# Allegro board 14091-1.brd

Outline 185 x 230 mm; copper layers: TOP, L2GND, L3, L4, L5GND, BOTTOM. Coordinates in mm from the lower left corner of the outline.
Outline path: 0,229 0,154.5 arc(0.59,153.09) 2,152.5 arc(3.41,151.91) 4,150.5 4,133 arc(4.29,132.29) 5,132 27,132 arc(27.71,131.71) 28,131 28,76 arc(27.71,75.29) 27,75 21,75 arc(20.29,74.71) 20,74 20,1 arc(20.29,0.29) 21,0 154,0 arc(154.71,0.29) 155,1 155,14 arc(155.29,14.71) 156,15 169,15 arc(169.71,15.29) 170,16 170,58.9 arc(170.29,59.61) 171,59.9 176,59.9 arc(176.71,60.19) 177,60.9 177,65.9 arc(177.29,66.61) 178,66.9 184,66.9 arc(184.71,67.19) 185,67.9 185,104.34 182,104.34 arc(180.25,106.09) 182,107.84 185,107.84 185,161.4 arc(184.71,162.11) 184,162.4 171,162.4 arc(170.29,162.69) 170,163.4 170,229 arc(169.71,229.71) 169,230 1,230 arc(0.29,229.71) 0,229 ; 24.75,51.4 25.25,51.4 arc(27.5,49.15) 25.25,46.9 24.75,46.9 arc(22.5,49.15) 24.75,51.4 ; 162.75,225.25 arc(165,227.5) 167.25,225.25 167.25,224.75 arc(165,222.5) 162.75,224.75 162.75,225.25

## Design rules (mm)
constraint set DEFAULT: min track width 0.127, pair gap 0.102
net group AUD_LINK_BCLK: nets AUD_LINK_BCLK HDA_BITCLK_CPU
net group CLK_WLAN_N: nets CLK_WLAN_N NGFF_REFCLKN0
net group CLK_WLAN_P: nets CLK_WLAN_P NGFF_REFCLKP0
net group DP_LANE0N_C: nets DP_LANE0N_C EDP_TX_CPU_N0
net group DP_LANE0P_C: nets DP_LANE0P_C EDP_TX_CPU_P0
net group DP_LANE1N_C: nets DP_LANE1N_C EDP_TX_CPU_N1
net group DP_LANE1P_C: nets DP_LANE1P_C EDP_TX_CPU_P1
net group DP_LANE2N_C: nets DP_LANE2N_C EDP_TX_CPU_N2
net group DP_LANE2P_C: nets DP_LANE2P_C EDP_TX_CPU_P2
net group DP_LANE3N_C: nets DP_LANE3N_C EDP_TX_CPU_N3
net group DP_LANE3P_C: nets DP_LANE3P_C EDP_TX_CPU_P3
net group GND: nets GND_AUD VSS_MECH
net group GPU_ODT-MW: nets ODTA0 ODTA1
net group HDMI1_CK+: nets HDMI1_CK+ HDMI1_CK+_C
net group HDMI1_CK-: nets HDMI1_CK- HDMI1_CK-_C
net group HDMI1_D0+: nets HDMI1_D0+ HDMI1_D0+_C
net group HDMI1_D0-: nets HDMI1_D0- HDMI1_D0-_C
net group HDMI1_D1+: nets HDMI1_D1+ HDMI1_D1+_C
net group HDMI1_D1-: nets HDMI1_D1- HDMI1_D1-_C
net group HDMI1_D2+: nets HDMI1_D2+ HDMI1_D2+_C
net group HDMI1_D2-: nets HDMI1_D2- HDMI1_D2-_C
net group HDMI1_DATA_CPU_N0: nets HDMI1_DATA_CPU_N0 HDMI1_DATA_IC_N0
net group HDMI1_DATA_CPU_N1: nets HDMI1_DATA_CPU_N1 HDMI1_DATA_IC_N1
net group HDMI1_DATA_CPU_N2: nets HDMI1_DATA_CPU_N2 HDMI1_DATA_IC_N2
net group HDMI1_DATA_CPU_N3: nets HDMI1_DATA_CPU_N3 HDMI1_DATA_IC_N3
net group HDMI1_DATA_CPU_P0: nets HDMI1_DATA_CPU_P0 HDMI1_DATA_IC_P0
net group HDMI1_DATA_CPU_P1: nets HDMI1_DATA_CPU_P1 HDMI1_DATA_IC_P1
net group HDMI1_DATA_CPU_P2: nets HDMI1_DATA_CPU_P2 HDMI1_DATA_IC_P2
net group HDMI1_DATA_CPU_P3: nets HDMI1_DATA_CPU_P3 HDMI1_DATA_IC_P3
net group HDMI_LANE0_DN: nets HDMI_LANE0_DN HDMI_LANE0_IC_DN
net group HDMI_LANE0_DP: nets HDMI_LANE0_DP HDMI_LANE0_IC_DP
net group HDMI_LANE1_DN: nets HDMI_LANE1_DN HDMI_LANE1_IC_DN
net group HDMI_LANE1_DP: nets HDMI_LANE1_DP HDMI_LANE1_IC_DP
net group HDMI_LANE2_DN: nets HDMI_LANE2_DN HDMI_LANE2_IC_DN
net group HDMI_LANE2_DP: nets HDMI_LANE2_DP HDMI_LANE2_IC_DP
net group HDMI_LANE3_DN: nets HDMI_LANE3_DN HDMI_LANE3_IC_DN
net group HDMI_LANE3_DP: nets HDMI_LANE3_DP HDMI_LANE3_IC_DP
net group HSI_C_DN8: nets HSI_C_DN8 PCIE_RX_CPU_N8
net group HSI_C_DP8: nets HSI_C_DP8 PCIE_RX_CPU_P8
net group HSI_LAN_DN1_R: nets HSI_LAN_DN1_R PCIE_RX_CPU_N4
net group HSI_LAN_DP1_R: nets HSI_LAN_DP1_R PCIE_RX_CPU_P4
net group LAN_MDI2_DN: nets LAN_MDI2_DN LAN_MDI2_DN_R
net group LAN_MDI2_DP: nets LAN_MDI2_DP LAN_MDI2_DP_R
net group LAN_MDI3_DN: nets LAN_MDI3_DN LAN_MDI3_DN_R
net group LAN_MDI3_DP: nets LAN_MDI3_DP LAN_MDI3_DP_R
net group M1_SMB_CLK: nets M1_SMB_CLK SMB_CLK_RESUME
net group M1_SMB_DATA: nets M1_SMB_DATA SMB_DATA_RESUME
net group M_A_CLK0: nets M_A_CLK0 M_A_CLK#0
net group M_A_CLK1: nets M_A_CLK1 M_A_CLK#1
net group M_B_CLK0: nets M_B_CLK0 M_B_CLK#0
net group M_B_DQS0: nets M_B_DQS_DN0 M_B_DQS_DP0
net group M_B_DQS1: nets M_B_DQS_DN1 M_B_DQS_DP1
net group M_B_DQS2: nets M_B_DQS_DN2 M_B_DQS_DP2
net group M_B_DQS3: nets M_B_DQS_DN3 M_B_DQS_DP3
net group M_B_DQS4: nets M_B_DQS_DN4 M_B_DQS_DP4
net group M_B_DQS5: nets M_B_DQS_DN5 M_B_DQS_DP5
net group M_B_DQS6: nets M_B_DQS_DN6 M_B_DQS_DP6
net group M_B_DQS7: nets M_B_DQS_DN7 M_B_DQS_DP7
net group NGFF_PCIE0_RXN: nets NGFF_PCIE0_RXN PCIE_RX_CPU_N5
net group NGFF_PCIE0_RXP: nets NGFF_PCIE0_RXP PCIE_RX_CPU_P5
net group PCIE_TX_CON_N4: nets PCIE_TX_CON_N4 PCIE_TX_CPU_N4
net group PCIE_TX_CON_N8: nets PCIE_TX_CON_N8 PCIE_TX_CPU_N8
net group PCIE_TX_CON_P4: nets PCIE_TX_CON_P4 PCIE_TX_CPU_P4
net group PCIE_TX_CON_P8: nets PCIE_TX_CON_P8 PCIE_TX_CPU_P8
net group PEG_C_RXN0: nets PEG_C_RXN0 PEG_RXN0
net group PEG_C_RXN1: nets PEG_C_RXN1 PEG_RXN1
net group PEG_C_RXN2: nets PEG_C_RXN2 PEG_RXN2
net group PEG_C_RXN3: nets PEG_C_RXN3 PEG_RXN3
net group PEG_C_RXP0: nets PEG_C_RXP0 PEG_RXP0
net group PEG_C_RXP1: nets PEG_C_RXP1 PEG_RXP1
net group PEG_C_RXP2: nets PEG_C_RXP2 PEG_RXP2
net group PEG_C_RXP3: nets PEG_C_RXP3 PEG_RXP3
net group PEG_C_TXN0: nets PEG_C_TXN0 PEG_TXN0
net group PEG_C_TXN1: nets PEG_C_TXN1 PEG_TXN1
net group PEG_C_TXN2: nets PEG_C_TXN2 PEG_TXN2
net group PEG_C_TXN3: nets PEG_C_TXN3 PEG_TXN3
net group PEG_C_TXP0: nets PEG_C_TXP0 PEG_TXP0
net group PEG_C_TXP1: nets PEG_C_TXP1 PEG_TXP1
net group PEG_C_TXP2: nets PEG_C_TXP2 PEG_TXP2
net group PEG_C_TXP3: nets PEG_C_TXP3 PEG_TXP3
net group PEG_CLK_CPU: nets PEG_CLK_CPU PEG_CLK_XDP
net group PEG_CLK_CPU#: nets PEG_CLK_CPU# PEG_CLK_XDP#
net group RCOMP_PCIE: nets PEG_RCOMPN_CPU PEG_RCOMPP_CPU
net group SD_CLK_C_1: nets SD_CLK_C_1 SP3
net group SD_CMD: nets SD_CMD SP4
net group SD_DAT0: nets SD_DAT0 SP2
net group SD_DAT1: nets SD_DAT1 SP1
net group SD_DAT2: nets SD_DAT2 SP6
net group SD_DAT3: nets SD_DAT3 SP5
net group SIDE_USB3_RX0+: nets SIDE_USB3_RX0+ USB30_RX_CPU_P0
net group SIDE_USB3_RX0-: nets SIDE_USB3_RX0- USB30_RX_CPU_N0
net group SIDE_USB3_RX1+: nets SIDE_USB3_RX1+ USB30_RX_CPU_P1
net group SIDE_USB3_RX1-: nets SIDE_USB3_RX1- USB30_RX_CPU_N1
net group SMB_CLK_MAIN: nets SMB_CLK_MAIN XDP_SMBCLK
net group SMB_DATA_MAIN: nets SMB_DATA_MAIN XDP_SMBDAT
net group SPI_CS0_N: nets SPI_CS0_N SPI_CS_CPU_N0
net group STRAP: nets GPP_B18/GSPI0_MOSI GPP_B22/GSPI1_MOSI
net group TRANSFORNER_20_10: nets MCT_R_1 XRF_TDC2
net group USB2_N0: nets USB2_N0 USBP0N_EXT
net group USB2_N1: nets USB2_N1 USB2_OUT_N1
net group USB2_N3: nets USB2_N3 USB3N_EXT
net group USB2_N4: nets USB2_N4 USB_PCH_DN4_NN
net group USB2_N5: nets USB2_N5 USB_TOUCH_N
net group USB2_N6: nets USB2_N6 USB2_NGFF_N6
net group USB2_NGFF_P6: nets USB2_NGFF_P6 USB2_P6
net group USB2_OUT_P1: nets USB2_OUT_P1 USB2_P1
net group USB2_P0: nets USB2_P0 USBP0P_EXT
net group USB2_P3: nets USB2_P3 USB3P_EXT
net group USB2_P4: nets USB2_P4 USB_PCH_DP4_PP
net group USB2_P5: nets USB2_P5 USB_TOUCH_P
net group USB2N_EXT: nets USB2_N2 USB2N_EXT
net group USB2P_EXT: nets USB2_P2 USB2P_EXT
net group AUD_LINK_SDO: nets AUD_LINK_SDO AUD_LINK_SDO_N HDA_SDOUT_CPU
net group AUDIO_AMP-MW: nets TPA3131_FAULT#
net group AUDIO_AMP_15: nets AMP_SPKR_L AMP_SPKR_R AMP_SWITCH_C_L AMP_SWITCH_C_R PORTC_SPK_L PORTC_SPK_L_1 PORTC_SPK_R PORTC_SPK_R_1 SCALAR_OUT_L SCALAR_OUT_L_C SCALAR_OUT_R SCALAR_OUT_R_C SPEAKER1_L1 SPEAKER1_R1 SPKR_IN_L SPKR_IN_R TP3131_GVDD TPA3131_GAIN TPA3131_LINN TPA3131_LINN_1 TPA3131_MUTE TPA3131_PLIMIT TPA3131_RINN TPA3131_RINN_1
net group AUDIO_DMIC_MW: nets AUD_DMIC_CLK AUD_DMIC_CLK_R AUD_DMIC_CLK_R_1 AUD_DMIC_DATA AUD_DMIC_DATA_R
net group AUDIO_HDA: nets AUD_BEEP_C AUD_BEEP_R AUD_LINK_RST_N AUD_LINK_RST_N_R AUD_LINK_SDIN AUD_LINK_SDIN_1 AUD_LINK_SDO_1 AUD_LINK_SDO_R1 AUD_LINK_SYNC BUZZER_SPKR_R HDA_RST#_CPU HDA_SYNC_CPU PCH_AUD_RST_N PCH_AUD_RST_N_1 SENSE_A SENSE_A_C SENSE_B SLEEVE_G SPDIF_IC
net group AUDIO_IO: nets AUD_GP3 EAPD_DEPOP HPOL_CON HPOR_CON HPOUT-JD HPOUT-L HPOUT-R LINE2-VREFO LINEOUT-JD LINEOUT-L LINEOUT-R LINEOUT_C-L LINEOUT_C-R LINEOUT_CON-L LINEOUT_CON-R MIC2-L MIC2-L-1 MIC2-R MIC2-R-1 MIC2-VREFO-L MIC2-VREFO-R
net group AUDIO_IO_REF: nets JDREF MIC-CAP VRP
net group AUDIO_SPK_CN: nets SPKR_L+_C SPKR_L+_SNB SPKR_L-_C SPKR_L-_SNB SPKR_OUT_L+ SPKR_OUT_L- SPKR_OUT_R+ SPKR_OUT_R- SPKR_R+_C SPKR_R+_SNB SPKR_R-_C SPKR_R-_SNB TPA3131_BSNL TPA3131_BSNR TPA3131_BSPL TPA3131_BSPR
net group CARD_READER-MWS: nets SD_CD# SD_WP SP7
net group CFG-MW: nets BPM_CPU_N2 BPM_CPU_N3 CFG0 CFG1 CFG2 CFG3 CFG4 CFG5 CFG6 CFG7 CFG8 CFG9 CFG10 CFG11 CFG12 CFG13 CFG14 CFG15 CFG16 CFG17 CFG18 CFG19
net group CHARGER_4_5-MW: nets AC_IN AC_OK# AC_PRESENT AC_PROTECT AD_IA AD_IA_HW1 AD_IA_HW2 AD_OFF BAT_ALERT BAT_IN# BAT_IN#_1 CHG_ON# SYS_PRES
net group CLOCK-MW: nets CK_P_33M_EC LPC_CLK0 LPC_CLK0_R LPC_CLK1 LPC_CLK1_R LPC_CLK_D SUS_CLK SUS_CLK_PCH
net group CONVERTER_4_5-MW: nets LEDC_ISET LPF RT SSTCMP SSTCMP_1 STATUS VREF
net group CONVERTER_10_10: nets ISEN1 ISEN2 ISEN3 ISEN4 ISW OZ554_PWM RTN1 RTN2 RTN3 RTN4
net group CONVERTER_20_10: nets LDR LDR_1 OZ554_VIN SNB
net group DP_AUXN_C: nets DP_AUXN_C EDP_AUX_CPU_N RTD_PIN122
net group DP_AUXP_C: nets DP_AUXP_C EDP_AUX_CPU_P RTD_PIN121
net group DP_HPD-MW: nets DDSP_B_HPD_CONN DP_HPD EDP_HPD_CPU HDMI1_OUT_HPD HDMI_HDCP_READY HDMI_HPDET
net group FAN_PWM: nets BKLT_ADJ CPU_FAN_CTRL_SIO CPU_FAN_TACH_SIO DPLVDS_PWMIN DPLVDS_PWMOUT L_BKLTCTL LVDS_BL_ADJ SIO_LVDS_BL_ADJ
net group FFS_4_5-MW: nets FALL_INT2 FFS_INT1 FFS_INT1_C FFS_INT2_APU FFS_INT2_C FFS_INT2_Q
net group GPIO_4-MW: nets AC_OK#_C AD_IA_EC AD_IA_HW1_C AD_IA_HW1_EC AD_IA_HW2_C AD_IA_HW2_EC AD_OFF_C ADAPTOR_PSID ADAPTOR_PSID_EC ADAPTOR_PSID_R BAT_IN#_C BIOS_REQ BIST_DISABLE BIST_EN_INV BIST_EN_SIO BIST_ENABLE BIST_ENABLE_1 BIST_PIN25 BOARD1 BOARD2 BOARD3 CHAR_CTL1 CHAR_CTL2 CHAR_CTL3 CHAR_EN CHAR_ILIM_SEL CHAR_USBOC# CHG_ON#_C CR_CLKREQ_R CRCLK_REQ_N DDC_WP DDC_WP_1 DET_HDMI# DET_HDMI_C DISP_UTIL_CPU DPLVDS_HPD EAPD_DEPOP_1 EAPD_DEPOP_2_D EC_PWREN EC_SCI# EC_SMI# EDID_RDY ESPI_RST# EXT_PWR_GATE# FFS_INT1_SIO FIVR_EN_R FLASH_WP GPD2/LAN_WAKE# GPIO GPIO17_THERMAL_INT GPIO19_CTF GPP_B23/SML1ALERT# GPP_C2/SMBALERT# GPP_C5/SML0ALERT# GPU_THERMAL_INT H_RCIN# HDMI_DET1 HDMI_DET_SIO HDMI_IN_DET#_R HP_MUTE IO_SMI_N ITP_PMODE JACK_PSID LAN_DISABLE_N LPC_CLKRUN#_CPU LPC_PME# LPC_PME_N LVDS_DET_A* LVDS_DET_B* MINI_POWER_CTRL MODEL_ID_DET MPCIE_DISABLE_N MS_INS# NGFF_ALERT# NGFF_BT_DISABLE NGFF_DETECT_PCIE NGFF_DETECT_PCIE_C NGFF_DETECT_USB NGFF_DETECT_USB_C NGFFCLK_REQ_N OS_MODE_SEL OSD_BIST_N OSD_CONTROL_SEL OSD_DN OSD_DN_CPU OSD_DN_IC OSD_DN_R OSD_MENU OSD_MENU_CPU OSD_MENU_IC OSD_MENU_R OSD_MENU_SIO OSD_UP OSD_UP_CPU OSD_UP_IC OSD_UP_R PANEL_SEL1_CABLE_C PANEL_SEL1_CABLE_S PANEL_SEL2_CABLE_C PANEL_SEL2_CABLE_S PANEL_SEL3_CABLE_C PANEL_SEL3_CABLE_S PC_MONITOR_SW PCB_VER_ID PCH_CHAR_CTL3 PCIE_CLKREQ1_CPU_N PCIE_CLKREQ2_CPU_N PCIE_CLKREQ3_CPU_N PEG_CLKREQ0_CPU# PEG_CLKREQ4_CPU# PEG_CLKREQ5_CPU# PIRQA# PM_CLKRUN#_EC PROC_SELECT# PSID_D PSID_D_1 PSID_G PW_CLEAR PWR_CHG_AD_OFF PWRCN_DET_N RTD_PIN2 RTD_PIN105 RTD_PIN119 SCALAR_ACK SCALAR_MUTE SD_WAKE#_IC SER_IRQ_R SERIRQ_CPU SHDN_MUTE_AP_CTL SIO_HDD_LED SIO_HDD_LED_1 SIO_INT# SIO_INT_C SIO_SCI# SKEW1 SKEW2 SKEW3 SKTOCC# SLP_WLAN_N SMBUS_MS SPKR_DET SPKR_DET_C THERMAL_SHUT#_SIO USB_OC#0_1 USB_OC#2_3 VSS_AY3 WEBCAM_DET WP_PRO
net group GPIO_PWR_CTRL: nets +V_VREF_PATH1 +V_VREF_PATH2 +V_VREF_PATH3 AD_OFF_L EC_3P3_CTL EC_3P3_CTL_2 EC_3P3_CTL_3 HDA_SPKR HP_MUTE_D HP_MUTE_L LVDS_PU_6_1 ME_CNTL1 N35415300 N35418666 N37189306 PANEL_ON1 PANEL_ON2 PANEL_ON3 PC_MONITOR_SW_G PCH_BKLT_PWM_1 PCH_PWROK_C_1 PCH_PWROK_C_2 PCH_PWROK_C_3 PD4405_A PD4405_K PQ4206_D PQ4406_2 PQ4406_3 PQ4406_5 PQ4406_6 PQ4409_C PQ4409_E PWR_CHG_AD_OFF_R PWR_VDDQ_PG_N PWRGD_3V_B PWRGD_3V_C RSMRST_N_B SA0_DIMA SA0_DIMB SA1_DIMA SA1_DIMB SCALAR_PC_SW1 SCALAR_PC_SW2 SCALAR_PC_SW3 SCALAR_PC_SW4 SCALAR_PC_SW5 SIO_PSON_D SLP_SUSB_C SLP_SUSB_R THERMTRIP#_EC_N TPA3113_SD TPA3113_SD1# VCCIO_EN_C_1 VCCIO_EN_C_2 VCCIO_EN_C_3 VCCIO_EN_C_4 VR_EN_C_1 VR_EN_C_2
net group GPU_ADDRESS-MW: nets MAA0 MAA1 MAA2 MAA3 MAA4 MAA5 MAA6 MAA7 MAA8 MAA9 MAA10 MAA11 MAA12 MAA13 MAA14 MAA_BA0 MAA_BA1 MAA_BA2
net group GPU_CTRL-MW: nets CASA0# CASA1# CKEA0 CKEA1 CSA0#_0 CSA1#_0 RASA0# RASA1# WEA0# WEA1#
net group GPU_DATA-MW: nets DQMA0 DQMA1 DQMA2 DQMA3 DQMA4 DQMA5 DQMA6 DQMA7 MDA0 MDA1 MDA2 MDA3 MDA4 MDA5 MDA6 MDA7 MDA8 MDA9 MDA10 MDA11 MDA12 MDA13 MDA14 MDA15 MDA16 MDA17 MDA18 MDA19 MDA20 MDA21 MDA22 MDA23 MDA24 MDA25 MDA26 MDA27 MDA28 MDA29 MDA30 MDA31 MDA32 MDA33 MDA34 MDA35 MDA36 MDA37 MDA38 MDA39 MDA40 MDA41 MDA42 MDA43 MDA44 MDA45 MDA46 MDA47 MDA48 MDA49 MDA50 MDA51 MDA52 MDA53 MDA54 MDA55 MDA56 MDA57 MDA58 MDA59 MDA60 MDA61 MDA62 MDA63
net group GPU_JTAG_4-6-MW: nets JTAG_TCK_VGA JTAG_TDI_VGA JTAG_TDO_VGA JTAG_TMS_VGA JTAG_TRST#_VGA
net group GPU_OTHER_4-6-MW: nets CLKTESTA CLKTESTA_C CLKTESTB CLKTESTB_C CTF_TRIP CTFB GPIO19_CTF_R GPIO_SVC GPIO_SVD GPIO_SVT GPU_CLKA0_T GPU_CLKA1_T GPU_GPIO16 GPU_SCL GPU_SDA GPU_THERM_SHUTDOWN* GPU_VCC3_CTL GPU_VCC3_CTL_2 GPU_VCC3_CTL_3 GPU_WAKEB GPU_XO_IN GPU_XO_IN2 MEM_CALRP0 MLPS_EN# PCIE_CALR_RX PCIE_CALR_TX PS_0 PS_1 PS_2 PS_3 VRAM_ZQ1 VRAM_ZQ2 VRAM_ZQ3 VRAM_ZQ4
net group GPU_VREF: nets GPU_VREFG MVREFDA MVREFSA VRAM1_VREFCA VRAM1_VREFDQ VRAM2_VREFCA VRAM2_VREFDQ VRAM3_VREFCA VRAM3_VREFDQ VRAM4_VREFCA VRAM4_VREFDQ
net group HDMI-MW: nets CFG DCIN_EN DDCBUF EQ ISET PD_N PRE REXT SB5_33_CT1 SB5_33_CT2
net group HDMI_PWR: nets V_5P0_HDMI_CONN_L
net group LAN_OTHER_4-5-MW: nets LAN_RSET LANCLK_REQ_N LANCLK_REQ_U_N RTL_ISOLATE_N RTL_ISOLATE_N_1 RTL_ISOLATE_N_2
net group LED_10_6: nets BATT_AMBER_LED# BATT_AMBER_LED#_C BATT_WHITE_LED# BATT_WHITE_LED#_C LAN_LEDACT_R# LINK_ACTIVITY_N LINK_PWR PB_IN_SW1 PCH_SATA_LED_1 PCH_SATA_LED_R PWR_LED_YELLOW_C PWR_LED_YELLOW_C2 SATA_LED_N SATA_LED_N_C_1 SIO_GREEN SIO_GREEN_PWM SIO_GREEN_PWM_C_1 SIO_YELLOW SPEED_100*_CON SPEED_100_N SPEED_1000*_CON SPEED_1000_N SUS_LED_GREEN_C SUS_LED_GREEN_C2
net group LPC-MW: nets EXT_RST# FWH_ID0 INIT_3V L_AD0 L_AD1 L_AD2 L_AD3 L_FRAME_N L_FRAME_N_R LAD0_FWH0_EC LAD1_FWH1_EC LAD2_FWH2_EC LAD3_FWH3_EC LDRQ# LDRQ#_EC LFRAMEJ_FW4_EC PLTRST*_EC
net group M_A_CLK TO CTRL: nets M_A_CKE0 M_A_CKE1 M_A_CS#0 M_A_CS#1 M_A_ODT0 M_A_ODT1
net group M_A_CLK TO DQS: nets M_A_DQS_DN0 M_A_DQS_DN1 M_A_DQS_DN2 M_A_DQS_DN3 M_A_DQS_DN4 M_A_DQS_DN5 M_A_DQS_DN6 M_A_DQS_DN7 M_A_DQS_DP0 M_A_DQS_DP1 M_A_DQS_DP2 M_A_DQS_DP3 M_A_DQS_DP4 M_A_DQS_DP5 M_A_DQS_DP6 M_A_DQS_DP7
net group M_A_COMMAND: nets M_A_A0 M_A_A1 M_A_A2 M_A_A3 M_A_A4 M_A_A5 M_A_A6 M_A_A7 M_A_A8 M_A_A9 M_A_A10 M_A_A11 M_A_A12 M_A_A13 M_A_A14 M_A_A15 M_A_BS0 M_A_BS1 M_A_BS2 M_A_CAS# M_A_RAS# M_A_WE#
net group M_A_DATA0: nets M_A_DQ0 M_A_DQ1 M_A_DQ2 M_A_DQ3 M_A_DQ4 M_A_DQ5 M_A_DQ6 M_A_DQ7
net group M_A_DATA1: nets M_A_DQ8 M_A_DQ9 M_A_DQ10 M_A_DQ11 M_A_DQ12 M_A_DQ13 M_A_DQ14 M_A_DQ15
net group M_A_DATA2: nets M_A_DQ16 M_A_DQ17 M_A_DQ18 M_A_DQ19 M_A_DQ20 M_A_DQ21 M_A_DQ22 M_A_DQ23
net group M_A_DATA3: nets M_A_DQ24 M_A_DQ25 M_A_DQ26 M_A_DQ27 M_A_DQ28 M_A_DQ29 M_A_DQ30 M_A_DQ31
net group M_A_DATA4: nets M_A_DQ32 M_A_DQ33 M_A_DQ34 M_A_DQ35 M_A_DQ36 M_A_DQ37 M_A_DQ38 M_A_DQ39
net group M_A_DATA5: nets M_A_DQ40 M_A_DQ41 M_A_DQ42 M_A_DQ43 M_A_DQ44 M_A_DQ45 M_A_DQ46 M_A_DQ47
net group M_A_DATA6: nets M_A_DQ48 M_A_DQ49 M_A_DQ50 M_A_DQ51 M_A_DQ52 M_A_DQ53 M_A_DQ54 M_A_DQ55
net group M_A_DATA7: nets M_A_DQ56 M_A_DQ57 M_A_DQ58 M_A_DQ59 M_A_DQ60 M_A_DQ61 M_A_DQ62 M_A_DQ63
net group M_B_CLK1: nets M_B_CLK#1
net group M_B_CLK TO CONTROL: nets M_B_CKE0 M_B_CKE1 M_B_CLK1 M_B_CS#0 M_B_CS#1 M_B_ODT0 M_B_ODT1
net group M_B_COMMAND: nets M_B_A0 M_B_A1 M_B_A2 M_B_A3 M_B_A4 M_B_A5 M_B_A6 M_B_A7 M_B_A8 M_B_A9 M_B_A10 M_B_A11 M_B_A12 M_B_A13 M_B_A14 M_B_A15 M_B_BS0 M_B_BS1 M_B_BS2 M_B_CAS# M_B_RAS# M_B_WE#
net group M_B_DATA0: nets M_B_DQ0 M_B_DQ1 M_B_DQ2 M_B_DQ3 M_B_DQ4 M_B_DQ5 M_B_DQ6 M_B_DQ7
net group M_B_DATA1: nets M_B_DQ8 M_B_DQ9 M_B_DQ10 M_B_DQ11 M_B_DQ12 M_B_DQ13 M_B_DQ14 M_B_DQ15
net group M_B_DATA2: nets M_B_DQ16 M_B_DQ17 M_B_DQ18 M_B_DQ19 M_B_DQ20 M_B_DQ21 M_B_DQ22 M_B_DQ23
net group M_B_DATA3: nets M_B_DQ24 M_B_DQ25 M_B_DQ26 M_B_DQ27 M_B_DQ28 M_B_DQ29 M_B_DQ30 M_B_DQ31
net group M_B_DATA4: nets M_B_DQ32 M_B_DQ33 M_B_DQ34 M_B_DQ35 M_B_DQ36 M_B_DQ37 M_B_DQ38 M_B_DQ39
net group M_B_DATA5: nets M_B_DQ40 M_B_DQ41 M_B_DQ42 M_B_DQ43 M_B_DQ44 M_B_DQ45 M_B_DQ46 M_B_DQ47
net group M_B_DATA6: nets M_B_DQ48 M_B_DQ49 M_B_DQ50 M_B_DQ51 M_B_DQ52 M_B_DQ53 M_B_DQ54 M_B_DQ55
net group M_B_DATA7: nets M_B_DQ56 M_B_DQ57 M_B_DQ58 M_B_DQ59 M_B_DQ60 M_B_DQ61 M_B_DQ62 M_B_DQ63
net group M_EVENT_4_5-MW: nets SIO_MEM_EVENT_L
net group NGFF_CLCCK-MW: nets NGFF_CLKREQ0_N NGFF_CLKREQ1_N SUSCLK_NGFF
net group NGFF_OTHER-MW: nets NGFF_ALERT_N NGFF_CLKREQ0_NGFF# NGFF_CLKREQ1_N_TP NGFF_PEWAKE0_N NGFF_POWER_CTRL_1 NGFF_W_DISABLE1_N NGFF_W_DISABLE2_N
net group NGFF_PCIE0_TXN: nets NGFF_PCIE0_TXN PCIE_TX_CON_N5 PCIE_TX_CPU_N5
net group NGFF_PCIE0_TXP: nets NGFF_PCIE0_TXP PCIE_TX_CON_P5 PCIE_TX_CPU_P5
net group OSCILLATION-MW: nets 14MHZ_IN_SCALAR 14MHZ_OUT_SCALAR 14MHZ_OUT_SCALAR_C CK_48M_SIO CK_48M_SIO_C LAN_XTALI LAN_XTALO LAN_XTALO_C XTALIN XTALOUT
net group OTHER_4_5-MW: nets 1117 ADJ KDAT MCLK MDAT PB_IN_N_1 SYS_FAN_TACH1_1 SYS_FAN_TACH1_2 SYSTEM_FAN_PWM1_1 TP_DET
net group PANEL_CONTROL-MW: nets BKLT_EN BKLT_EN1 DPLVDS_BL_EN DPLVDS_PANEL_VCC LVDS_DET_B_C* LVDS_PU_5 LVDS_PU_6 LVDS_PU_24 PANEL_ON_1 PANEL_ON_2 PANEL_ON_3 PANEL_ON_4 PANEL_ON_5 PANEL_SEL1_CABLE PANEL_SEL1_CABLE_EC PANEL_SEL2_CABLE PANEL_SEL2_CABLE_EC PANEL_SEL3_CABLE PANEL_SEL3_CABLE_EC S_LVDS_BL_EN SCALAR_SIO_PU
net group PECI_THERMTRIP-MW: nets EC_PECI EC_PROCHOT# H_PROCHOT_N PECI_EC PECI_SIO PROCHOT#_CPU THERMTRIP#_CPU THERMTRIP#_EC TMDS_3V3
net group POWER_10_10: nets 3P3V_SPI CHAR_ILIM_HI CHAR_ILIM_LO DDC5V_HDMI DDC5V_HDMI_R HDMI_OUT_DDC_VCC OCS_48M_1 OCS_48M_2 PWR_VCCSA_VSP_RC RTD2482_VREF SD_VDD2 SIO_VREF VBAT_SIO VCCRTCEXT VSS_AY71
net group POWER_12_10_REF: nets RREF
net group POWER_20_5: nets +19V_AMP_AVCC ADC_1V2 AV12 AV12_L DV12S DV33_18 HDMI_5V PVCC_3V3_SDRAM V_3_CARD VCCK_1V2
net group POWER_40_5: nets 3D3V_AUX_EC AVCC_EC DPLL_PVDD HM_VCCP HM_VCCP_R MPV18 SIO_MAIN_VCC3 SIO_VCORE SPV10 SPV18
net group POWER_50_5: nets 1V_EOPIO 1V_VCCPRIM_CORE 3D3V_AUX_S5 3D3V_VGA_S0 DPLL_VDDC USBVCCTP
net group POWER_CPU_PLL_10_5: nets 1D8V_EDRAM 1D8V_SIP_S5 1D8V_VCCPGPPF 1D35V_VCCSFR_OC 1D35V_VDDQ_CPUCLK 1V_CPU_XDP_AB 1V_CPU_XDP_CD 1V_DCPDSW 1V_SIP_S5 1V_VCC19P2 1V_VCC24TBT 1V_VCCAMPHYPLL 1V_VCCAPLL 1V_VCCAPLLEBB 1V_VCCDTS 1V_VCCF24NS 1V_VCCF100 1V_VCCF100OC 1V_VCCF135 1V_VCCFHV 1V_VCCFUSEPRG 1V_VCCMPHYAON 1V_VCCSFR 1V_VCCSTG 1V_XDP_S5 3D3V_1D8V_VCCHDA 3D3V_1D8V_VCCPGPPA 3D3V_1D8V_VCCPGPPD 3D3V_1D8V_VCCPSPI 3D3V_VCCPGPPB 3D3V_VCCPGPPC 3D3V_VCCPGPPE 3D3V_VCCPGPPG 3D3V_VCCPRIM 3D3V_VCCPRTCPRIM +VCCPRTC_3P3
net group POWER_CPU_PLL_20_5: nets 1V_VCCPRIM 1V_VCCSRAM 3D3V_VCCPDSW
net group POWER_RTC_10_10: nets V_3P0_BAT_VREG VBAT1 VBAT1_R VBAT2
net group PWM_10_10: nets 62882_COMP_R 62882_FB_VSEN 62882_NTC_R AD+_G_1 AD+_G_2 AUD_LINK_RST_N_2 BIST_DISABLE_1 BIST_EN DC_IN_D DDR_VREF_S3 EAPD_DEPOP_2 LAN_DISABLE_N_1 LAN_DISABLE_N_2 LED_5VSB OSD_BIST_N_1 PRW_VGA_CORE_RBIAS PSYS PWR_0D95V_VGA_FB PWR_0D95V_VGA_FB_R1 PWR_0D95V_VGA_FB_R2 PWR_1D0V_CS PWR_1D0V_FB PWR_1D0V_FB_R PWR_1D0V_RF PWR_1D8V_EN PWR_1D8V_FB PWR_1D8V_FB_1 PWR_1D8V_VBYP PWR_1D8V_VOUT PWR_1D8V_VOUT_1 PWR_1D35V_VGA_FB_M PWR_1D35V_VGA_FB_M1 PWR_3D3V_ENTRIP2 PWR_3D3V_FB PWR_3D3V_FB2 PWR_5V3D3V_ENLDO PWR_5V3D3V_TON PWR_5V3V_SECFB PWR_5V_ENTRIP1 PWR_5V_FB1 PWR_CHG_ACDET PWR_CHG_CMPIN PWR_CHG_CMPIN_R PWR_CHG_CMPIN_RR PWR_CHG_ILIM PWR_CHG_IOUT PWR_CHG_NC PWR_V1P8A_FB PWR_VCCGT_COMP PWR_VCCGT_COMP_R PWR_VCCGT_CSCOMP PWR_VCCGT_CSREF PWR_VCCGT_CSSUM PWR_VCCGT_DIFFOUT PWR_VCCGT_DIFFOUT_R PWR_VCCGT_FB PWR_VCCGT_ILIM PWR_VCCGT_ILIM_NTC PWR_VCCGT_IOUT PWR_VCCGT_TSENSE PWR_VCCGT_TSENSE_NTC PWR_VCCGT_VSN PWR_VCCGT_VSN_G PWR_VCCGT_VSP PWR_VCCSA_COMP PWR_VCCSA_COMP_1 PWR_VCCSA_CSP PWR_VCCSA_CSP_R PWR_VCCSA_ILIM PWR_VCCSA_IOUT PWR_VCCSA_PWM PWR_VCCSA_VSN PWR_VCCSA_VSN_G PWR_VCCSA_VSP_ PWR_VCCSA_VSP_G PWR_VCORE_COMP PWR_VCORE_COMP_RC PWR_VCORE_CSP PWR_VCORE_CSP_NTC PWR_VCORE_DRON PWR_VCORE_ILIM PWR_VCORE_IOUT PWR_VCORE_TSENSE PWR_VCORE_TSENSE_NTC PWR_VCORE_VRHOT# PWR_VCORE_VSN PWR_VCORE_VSN_G PWR_VCORE_VSP PWR_VCORE_VSP_G PWR_VCORE_VSP_RC PWR_VDDQ_BOOT_1 PWR_VDDQ_CS PWR_VDDQ_FB PWR_VDDQ_SENSE PWR_VDDQ_TON PWR_VGA_CORE_COMP PWR_VGA_CORE_IMON PWR_VGA_CORE_ISEN1 PWR_VGA_CORE_ISEN2 PWR_VGA_CORE_ISUM- PWR_VGA_CORE_NTC PWR_VGA_CORE_RTN PWR_VGA_CORE_VSEN PWR_VGA_CORE_VW TSVDD VDDC_CT VR_TT# VREG_PCIAUX_PCH VREG_PCIAUX_PCH_1 VSUM_RC VSUM_RR
net group PWM_20_10: nets AUD_REGREF BOOT1_PHASE1 BQ24737_REGN CBN CBP CPVEE PWR_0D95V_VGA_SVIN PWR_1D0V_BOOT PWR_1D0V_BOOT_R PWR_1D0V_SNB PWR_1D8V_BOOT PWR_1D8V_BOOT_A PWR_1D8V_SNB PWR_1D8V_VCC PWR_3D3V_BOOT2 PWR_3D3V_BOOT2_1 PWR_3D3V_LDO3 PWR_3D3V_SNB PWR_5V_BOOT1 PWR_5V_BOOT1_1 PWR_5V_BYP1 PWR_5V_LDO PWR_5V_SNB PWR_CHG_BTST PWR_CHG_BTST_1 PWR_VCCGT_BSTA PWR_VCCGT_BSTA_R PWR_VCCGT_BSTB PWR_VCCGT_BSTB_R PWR_VCCGT_SNB1 PWR_VCCGT_SNB2 PWR_VCCSA_BST PWR_VCCSA_BST_RC PWR_VCORE_BST PWR_VCORE_BST_R PWR_VCORE_SNB PWR_VCORE_VCC PWR_VCORE_VRMP PWR_VDDQ_BOOT PWR_VDDQ_SNB PWR_VDDQ_VDD PWR_VDDQ_VDDP PWR_VDDQ_VTTREF PWR_VGA_CORE_BOOT1 PWR_VGA_CORE_FB PWR_VGA_CORE_FB2 PWR_VGA_CORE_SNB1 PWR_VGA_CORE_VCCP PWR_VGA_CORE_VDD PWR_VGA_CORE_VIN PX_EN SIO_VIN1 SIO_VIN3 SIO_VIN4 SIO_VIN5 TESTEN VREF_1
net group PWM_25_20: nets AD+_2
net group PWM_30_12: nets PWR_CHG_VCC
net group PWM_PHASE: nets PWR_1D0V_LGATE PWR_1D0V_UGATE PWR_CHG_HIDRV PWR_CHG_LODRV PWR_VCCGT_LGA PWR_VCCGT_LGB PWR_VCCGT_UGA PWR_VCCGT_UGB PWR_VCCSA_DRVH PWR_VCCSA_DRVL PWR_VCORE_LG PWR_VCORE_UG PWR_VDDQ_LGATE PWR_VDDQ_UGATE PWR_VGA_CORE_LGATE1A PWR_VGA_CORE_LGATE1B PWR_VGA_CORE_UGATE1
net group PWR_EN_4-MW: nets CPU_DDR_EN CPU_DDR_VTT_CNTL DGPU_EN DGPU_PWR_ EN# OZ554_ENA PANEL_OFF PANEL_OFF_C PWM_SW_EN PWR_0D95V_VGA_EN PWR_1D0V_EN PWR_1D35V_VGA_EN PWR_V1P8A_EN PWR_VCORE_EN PWR_VDDQ_EN RUN_EN1 RUN_EN2 RUN_EN_1P8V RUNPWR_R6 SB3V_EN SCALAR_EN SCALAR_EN_G SIO_AMD SVID_EN SLP_S4_N_EC VCC5_33_CT1 VCC5_33_CT2 VCC5_33_EN VCCSTG_EN VCCSTU_EN VCCSTU_EN_C_1 VCCSTU_EN_C_2 VCCSTU_EN_C_3 VCCSTU_EN_C_4 VR_EN VTT_EN
net group PWR_EN_4_10-MW: nets USB_EN USB_EN1 USB_EN2
net group PWRGD&RST_4-MW: nets 1P8V_PWR_PG ALL_SYS_PWRGD AMD_RST# BATLOW# BP_PWRGD_RST# DGPU_HOLD_RST# DGPU_PWROK DGPU_PWROK_S DRAM_RST DRAM_RST_R H_CPUPWRGD ICH_RSMRST_N_R KBRST_N LAN_DISABLE_N_3 LAN_DISABLE_N_4 LAN_DISABLE_V3 ME_CNTL MEM_RST NGFF_POWER_CTRL_V2 PANEL_ON PB_IN_N_1_C PCH_DPWROK PCH_PWROK PCH_RTCRST_DOWN PCH_RTCRST_PULLUP PCH_SIO_DPWROK PCH_SRTCRSTB_PULLUP PCH_WAKE_N PCIE_RST# PCIRST1# PCIRST3# PLTRST#_PCH PLTRST*_SIO PLTRST_CR PLTRST_LAN_N PLTRST_N PLTRST_SL_N PM_PCH_PWROK PM_PWRBTN_N PM_RSMRST_PWRGD_XDP PM_SLP_S3#_R PWR_0D95V_VGA_PG PWR_1D0V_PG PWR_1D8V_PG PWR_1D35V_VGA_PG PWR_5V3V_PGOOD PWR_V1P8A_PG PWR_VCORE_VR_RDY PWR_VDDQ_PG PWRBTN_N PWRGD_3V PWRGD_3V_B_1 PWRGD_3V_LL PWRGD_PS_L PWRGD_PS_L1 PWRGD_PS_L2 PWRGOOD_GPU PWROK3_1 PWROK3_1_R PWROK3_2 PWROK3_2_R RSMRST*_R RSMRST_N RSMRST_N_2 RSMRST_PWRGD# RTD_RESETB SD_WAKE_N SIO_PCIRSTIN# SIO_PSON_N SLP_S3_N SLP_S3_N_EC SLP_S3_N_R3 SLP_S4_N SLP_S4_N_C SLP_S4_N_SIO SLP_S5_N SLP_SUSB SM_DRAMRST# SM_DRAMRST#_R SM_INTRUDER# SUS_PWR_ACK SUS_PWR_ACK_SIO SUS_WARNB SUS_WARNB_SIO SYS_PWROK TP_PMODE_XDP_RST_R_N VCCST_GD_1 VCCST_GD_2 VCCST_GD_CPU VCCST_GD_R VR_RDY WAKE_N XDP_DBRESET# XDP_DBRESET_XDP# XDP_PREQ# XDP_SYS_PWROK
net group RCOMP: nets CFG_RCOMP CPU_POPIRCOMP EDRAM_OPIO_RCOMP EOPIO_RCOMP PCH_POPIRCOMP XCLK_BIASREF
net group RCOMP_EDP: nets EDP_RCOMP_CPU
net group RCOMP_SM: nets SM_RCOMP_0 SM_RCOMP_1 SM_RCOMP_2
net group RCOMP_UNUSED: nets CSI2_COMP EMMC_RCOMP SD_RCOMP
net group RCOMP_USB-MW: nets USBCOMP
net group SATAHDR_RX_DN0: nets SATA__RXN0_C SATA_RXN0_C_N SATAHDR_RX_DN0
net group SATAHDR_RX_DN1: nets SATA__RXN1_C SATA_RXN1_C_N SATAHDR_RX_DN1
net group SATAHDR_RX_DP0: nets SATA__RXP0_C SATA_RXP0_C_N SATAHDR_RX_DP0
net group SATAHDR_RX_DP1: nets SATA__RXP1_C SATA_RXP1_C_N SATAHDR_RX_DP1
net group SATAHDR_TX_DN0: nets SATA__TXN0_C SATA_TXN0_C_N SATAHDR_TX_DN0
net group SATAHDR_TX_DN1: nets SATA__TXN1_C SATA_TXN1_C_N SATAHDR_TX_DN1
net group SATAHDR_TX_DP0: nets SATA__TXP0_C SATA_TXP0_C_N SATAHDR_TX_DP0
net group SATAHDR_TX_DP1: nets SATA__TXP1_C SATA_TXP1_C_N SATAHDR_TX_DP1
net group SIDE_USB3_TX0+: nets SIDE_USB3_TX0+ USB3_TX0_EMI_DP USB30_TX_CPU_P0
net group SIDE_USB3_TX0-: nets SIDE_USB3_TX0- USB3_TX0_EMI_DN USB30_TX_CPU_N0
net group SIDE_USB3_TX1+: nets SIDE_USB3_TX1+ USB3_TX1_EMI_DP USB30_TX_CPU_P1
net group SIDE_USB3_TX1-: nets SIDE_USB3_TX1- USB3_TX1_EMI_DN USB30_TX_CPU_N1
net group SIO_IT8739-4_5-MW: nets EC_HDMI_PD_N EC_LAN_DISABLE_N IMS KBCLK SIO_ATXPG SIO_CE_N SIO_CLK_DB SIO_COPEN# SIO_DAT_DB SIO_HOLD# SIO_SCK SIO_SCK_R SIO_SI SIO_SO SIO_WP# SIO_WRST# SW_ON_N_SIO SYS_3VSB
net group SIO_IT8739-4_12-MW: nets A20GATE
net group SMBUS-MW: nets BATA_SCL_1 BATA_SDA_1 DDPB_CTRL_CLK_CONN DDPB_CTRL_DATA_CONN EC_SMB2_CLK EC_SMB2_DATA EESCL EESDA GPIO_VGA_03_DATA GPIO_VGA_03_DATA_R GPIO_VGA_04_CLK GPIO_VGA_04_CLK_R HDMI1_SCL HDMI1_SDA HDMI_SCL_IN HDMI_SCL_IN_C HDMI_SDA_IN HDMI_SDA_IN_C ISP_CLK1 ISP_DAT1 PCH_DVI_CLK PCH_DVI_DATA RTD_PIN123 RTD_PIN124 SIO_DEBUG_RX SIO_DEBUG_TX SIO_SMB2_CLK SIO_SMB2_DATA SIO_SMCLK0 SIO_SMDAT0 SMB0_CVT_CLK SMB0_CVT_DATA SMBUS_ISP SML0_CLK SML0_DATA SML1_CLK SML1_DATA
net group SPI-MW: nets CE CE#_1 GPIO_8_ROMSO GPIO_9_ROMSI GPIO_22_ROMCS# ROM_CS# ROM_SI_D3 ROM_SO_C4 SDIN SDIN_1 SDOUT SO_1 SPI_HOLD_CPU SPI_IO2 SPI_IO3 SPI_MISO SPI_MISO_ROM_1 SPI_SI_XDP SPI_SO_CPU SPI_WP_CPU SPI_WP_N_1 SPI_WP_XDP SST_HOLDJ_1 WP#_1
net group SPI_CLK: nets SPI_CLK SPI_CLK_1 SPI_CLK_CPU
net group SPI_CLK-MW: nets CLK CLK_1 GPIO_10_ROMSCK ROM_SLK_D4
net group SPI_MOSI: nets SPI_MOSI SPI_MOSI_1 SPI_SI_CPU
net group SVID-MW: nets PWR_VCORE_ALERT# PWR_VCORE_SCLK PWR_VCORE_SDIO VIDALERT#_CPU VIDALERT#_CPU_R VIDSCK_CPU VIDSCK_CPU_R VIDSOUT_CPU VIDSOUT_CPU_R
net group TP-MW: nets AC_IN_KBC# CATERR#_CPU CHAR_STATUS CPU_A16_TP CPU_A17_TP CPU_B16_TP CPU_B17_TP CPU_C18_TP CPU_C19_TP CPU_D4_TP CPU_D5_TP DDR0_PAR DDR1_PAR EC_SCI EC_VCORF GPP_B2/VRALERT# JENK# RDY# RSVD_TP_AK12 RSVD_TP_AK13 RSVD_TP_BA68 RSVD_TP_BA70 RSVD_TP_BB68 RSVD_TP_BB69 RSVD_TP_F65 RSVD_TP_G65 SLP_A_N SLP_LAN_N SLP_S0_N TCK TDI TDO TMS TP1_AY4 TP2_BB3 TP4_BB5 TP5_AU5 TP6_AT5 TP_DDPC_CTRLDATA TP_GPU_CLKREQ# TP_L_BKLTEN TP_L_VDDEN TP_NGFF_COEX1 TP_NGFF_COEX2 TP_NGFF_COEX3 TP_NGFF_LED1 TP_NGFF_LED2 TP_NGFF_MLDIR TP_SIO_VIN2 TPA3131_SYNC V0.85A_VID0 V0.85A_VID1 VCCCOREG0 VCCCOREG1
net group UART-MW: nets LPSS_UART2_RXD LPSS_UART2_TXD SIO_UART1_RX SIO_UART1_RX_R SIO_UART1_TX SIO_UART1_TX_R
net group VRD_4_12-MW: nets H_VID0 H_VID1 H_VID2 H_VID3 H_VID4 H_VID5 H_VID6 PM_DPRSLPVR PSI#
net group VREF_DIMM_20_20: nets M_VREF_CA_DIMMA M_VREF_CA_DIMMB M_VREF_DQ_DIM0 M_VREF_DQ_DIM1 M_VREF_DQ_DIMMA M_VREF_DQ_DIMMB V_SM_VREF_CNT
net group WLAN_CLINK_4_10-MW: nets CLINK_CLK_LAN CLINK_DATA_LAN CLINK_RST_LAN_N
net group XDP-MW: nets PCH_JTAG_TCK PCH_JTAG_TDI PCH_JTAG_TDO PCH_JTAG_TMS XDP_PRDY# XDP_PRSENT_PIN60 XDP_PRSNT_PIN1 XDP_TCK_JTAGX XDP_TCLK XDP_TCLK1 XDP_TDI XDP_TDO XDP_TDO_CPU XDP_TMS XDP_TRST#
nets with their own width: min track width 0.508; nets GND

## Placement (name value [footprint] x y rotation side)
AFTP1  -  [TPAD28]  35.47 58.29 0 top
BAT2  ACES-CONN20G-GP  [50290-0100N-001]  32 64.14 270 top
BT1  BAT-AAA-BAT-034-K01-GP  [AAA-BAT-034-K01]  147.48 91.7 270 top
BTRST1  JOWLE-CON2-5-GP  [A2541WV0-1EX2PA-6T]  113.83 112.01 90 top
C1  SCD1U16V2KX-3DLGP  [C402H22]  160.18 195.45 270 top
C4  SC4D7U10V3KX-DL-GP  [C603H36]  39.4 28.32 90 top
C5  SCD47U25V3KX-1-DL-GP  [C603H36]  29.5 29.21 0 bottom
C8  SC1KP50V2KX-1DLGP  [C402H22]  39.4 24.38 270 top
C10  SC100P50V2JN-3DLGP  [C402H22]  37.12 28.45 0 top
C14  SCD01U50V2KX-1DLGP  [C402H22]  37.12 115.7 270 top
C20  SC4D7U10V3KX-DL-GP  [C603H36]  34.58 108.46 180 bottom
C32  SCD1U25V3ZY-1-LL-GP  [C603H36]  48.42 38.23 0 top
C33  SC27P50V2JN-2DLGP  [C402H22]  42.71 23.11 0 top
C35  SC330P100V3JN-GP  [C603H36]  38.01 40.77 90 bottom
C36  SC1U100V6KX-3-GP  [C1206H75]  32.42 39.24 270 bottom
C37  SC1U100V6KX-3-GP  [C1206H75]  32.42 41.53 270 bottom
C38  SC1U100V6KX-3-GP  [C1206H75]  26.58 39.24 90 bottom
C39  SC1U100V6KX-3-GP  [C1206H75]  26.58 36.96 90 bottom
C40  SC1U100V6KX-3-GP  [C1206H75]  26.58 41.53 90 bottom
C43  SCD1U25V2KX-1-DL-GP  [C402H22]  37.12 24.77 180 top
C48  SC10U25V5KX-DL-GP  [C805H58]  8.42 214.5 0 bottom
C84  SCD1U16V2KX-3DLGP  [C402H22]  37.63 17.53 180 bottom
C87  SCD1U16V2KX-3DLGP  [C402H22]  41.82 23.11 0 top
C88  SCD1U16V2KX-3DLGP  [C402H22]  41.56 23.11 180 bottom
C91  SCD1U16V2KX-3DLGP  [C402H22]  160.43 115.82 90 top
C104  SC10U10V5KX-2DLGP  [C805H50]  166.15 119.76 0 top
C105  SC10U10V5KX-2DLGP  [C805H50]  168.18 119.76 0 top
C106  SCD1U16V2KX-3DLGP  [C402H22]  169.58 119.38 0 top
C109  SC10U6D3V3MX-DL-GP  [C603H36]  16.42 197.1 90 top
C110  SC1U25V3KX-1-DLGP  [C603H36]  16.42 195.83 90 top
C111  SCD1U16V2KX-3DLGP  [C402H22]  160.05 97.66 90 top
C112  SC10U10V5KX-2DLGP  [C805H50]  16.92 194.18 90 top
C113  SCD1U16V2KX-3DLGP  [C402H22]  160.05 96.77 90 top
C114  SCD01U50V2KX-1DLGP  [C402H22]  14 170.01 270 top
C115  SCD01U50V2KX-1DLGP  [C402H22]  14 170.9 270 top
C118  SCD01U50V2KX-1DLGP  [C402H22]  14 173.44 270 top
C119  SCD01U50V2KX-1DLGP  [C402H22]  14 174.33 270 top
C121  SC100P50V2JN-3DLGP  [C402H22]  156.75 67.97 90 top
C126  SC22P50V2JN-4DLGP  [C402H22]  156.24 77.09 90 top
C127  SC10U6D3V3MX-DL-GP  [C603H36]  157.01 72.9 0 top
C129  SC10U6D3V3MX-DL-GP  [C603H36]  155.86 74.93 270 top
C130  SCD1U25V2KX-1-DL-GP  [C402H22]  156.88 79.76 0 top
C131  SCD1U16V2KX-3DLGP  [C402H22]  158.02 73.28 0 top
C132  SC100P50V2JN-3DLGP  [C402H22]  158.15 70.05 0 top
C134  SC100P50V2JN-3DLGP  [C402H22]  172.63 82.42 0 top
C138  SC4D7U6D3V3KX-DLGP  [C603H36]  158.66 83.44 180 top
C139  SC4D7U6D3V3KX-DLGP  [C603H36]  159.93 83.44 180 top
C140  SC2D2U10V3KX-1DLGP-U  [C603H36]  162.47 82.3 270 top
C141  SCD01U50V2KX-1DLGP  [C402H22]  17.43 141.48 0 top
C142  SCD01U50V2KX-1DLGP  [C402H22]  18.32 141.48 0 top
C144  SC10U10V5KX-2DLGP  [C805H50]  162.52 84.71 270 top
C145  SCD1U16V2KX-3DLGP  [C402H22]  162.85 83.31 90 top
C146  SC10U10V5KX-2DLGP  [C805H50]  166.02 82.42 90 top
C147  SCD1U16V2KX-3DLGP  [C402H22]  165.26 81.03 270 top
C149  SCD01U50V2KX-1DLGP  [C402H22]  18.32 148.08 0 top
C150  SC1U10V2KX-1DLGP  [C402H22]  164.52 68.17 270 top
C151  SCD01U50V2KX-1DLGP  [C402H22]  17.43 148.08 0 top
C154  SC10U10V5KX-2DLGP  [C805H50]  169.63 79.4 90 top
C155  SC10U10V5KX-2DLGP  [C805H50]  169.58 81.41 90 top
C157  SC100P50V2JN-3DLGP  [C402H22]  170.98 75.31 0 top
C159  SC100P50V2JN-3DLGP  [C402H22]  170.98 73.41 0 top
C160  SC100P50V2JN-3DLGP  [C402H22]  170.98 77.47 180 top
C163  SCD1U16V2KX-3DLGP  [C402H22]  48.04 108.33 0 top
C170  SC1U10V2KX-1DLGP  [C402H22]  152.56 78.74 180 top
C179  SCD1U16V2KX-3DLGP  [C402H22]  144.56 42.67 90 top
C180  SCD1U10V2MX-3DLGP  [C402H22]  125.76 56.13 0 top
C181  SCD1U16V2KX-3DLGP  [C402H22]  142.65 44.7 270 top
C182  SCD1U16V2KX-3DLGP  [C402H22]  148.24 59.31 90 top
C183  SCD1U16V2KX-3DLGP  [C402H22]  140.75 43.81 90 top
C184  SCD1U16V2KX-3DLGP  [C402H22]  142.78 48.01 180 bottom
C185  SCD1U16V2KX-3DLGP  [C402H22]  125.26 50.16 0 top
C186  SCD1U16V2KX-3DLGP  [C402H22]  48.29 100.71 270 top
C187  SC22U6D3V5MX-2DLGP  [C805H54]  147.99 45.47 0 top
C188  SC1U10V2KX-1DLGP  [C402H22]  138.21 45.34 0 top
C189  SCD1U16V2ZY-2DLGP  [C402H22]  149.51 74.04 0 top
C190  SC1U10V2KX-1DLGP  [C402H22]  124.24 48.01 0 top
C191  SCD1U16V2KX-3DLGP  [C402H22]  127.06 63.8 180 top
C194  SCD1U16V2KX-3DLGP  [C402H22]  130.72 64.39 180 bottom
C195  SC22U6D3V5MX-2DLGP  [C805H54]  148.62 42.67 270 top
C197  SCD1U16V2ZY-2DLGP  [C402H22]  139.1 61.09 90 bottom
C201  SC100P50V2JN-3DLGP  [C402H22]  136.05 68.58 180 top
C202  SC4D7U6D3V3KX-DLGP  [C603H36]  39.53 18.06 180 bottom
C204  SCD1U16V2KX-3DLGP  [C402H22]  35.85 15.49 0 bottom
C207  SCD01U50V2KX-1DLGP  [C402H22]  47.79 94.61 90 top
C209  SC4D7U6D3V3KX-DLGP  [C603H36]  46.9 17.91 180 top
C211  SCD1U16V2KX-3DLGP  [C402H22]  141.26 49.43 90 bottom
C213  SCD1U16V2KX-3DLGP  [C402H22]  34.32 10.67 0 top
C214  SCD1U16V2KX-3DLGP  [C402H22]  48.42 87 90 bottom
C216  SCD1U16V2KX-3DLGP  [C402H22]  48.42 117.22 90 bottom
C231  SCD1U16V2KX-3DLGP  [C402H22]  139.1 49.45 270 bottom
C232  SCD1U50V3KX-DL-GP  [C603H35]  165.13 49.4 180 top
C233  SC10U25V5KX-DL-GP  [C805H58]  164.63 46.23 0 top
C235  SCD22U25V3KX-DL-GP  [C603H36]  163.23 42.67 270 top
C236  SCD027U50V3KX-DL-GP  [C603H36]  164.5 56.18 270 top
C238  SCD1U16V2KX-3DLGP  [C402H22]  30.26 30.23 180 top
C239  SCD22U25V3KX-DL-GP  [C603H36]  160.43 42.67 90 top
C240  SCD027U50V3KX-DL-GP  [C603H36]  158.4 55.24 0 top
C241  SCD027U50V3KX-DL-GP  [C603H36]  157.13 55.24 0 top
C242  SCD22U25V3KX-DL-GP  [C603H36]  156.62 42.67 270 top
C243  SC100P50V2JN-3DLGP  [C402H22]  155.48 54.61 90 top
C244  SCD22U25V3KX-DL-GP  [C603H36]  153.96 42.67 90 top
C245  SC1U16V3KX-2DLGP  [C603H36]  163.1 51.69 180 bottom
C246  SCD1U50V3KX-DL-GP  [C603H35]  154.34 50.93 180 top
C247  SCD1U50V3KX-DL-GP  [C603H35]  154.47 47.5 0 top
C248  SC10U25V5KX-DL-GP  [C805H58]  152.81 47.5 0 top
C249  SCD1U50V3KX-DL-GP  [C603H35]  122.84 11.3 270 bottom
C250  SC1U25V3KX-1-DLGP  [C603H36]  161.86 56.52 0 top
C252  SCD68U16V3KX-4-GP  [C603H36]  156.62 41.4 90 top
C253  SC1000P50V3JN-DLGP  [C603H36]  153.32 35.31 270 top
C254  SC1000P50V3JN-DLGP  [C603H36]  155.99 35.31 90 top
C255  SCD01U50V3KX-4DLGP  [C603H36]  152.43 37.08 180 bottom
C256  SCD01U50V3KX-4DLGP  [C603H36]  156.75 37.08 180 bottom
C257  SCD68U16V3KX-4-GP  [C603H36]  163.23 41.4 90 top
C258  SCD1U50V3KX-DL-GP  [C603H35]  69.76 33.02 90 top
C259  SC1000P50V3JN-DLGP  [C603H36]  162.09 35.31 90 top
C260  SC1U25V3KX-1-DLGP  [C603H36]  69.12 29.21 90 top
C261  SCD01U50V3KX-4DLGP  [C603H36]  162.85 37.21 180 bottom
C262  SCD01U50V2KX-1DLGP  [C402H22]  64.3 24.77 270 bottom
C267  SC100P50V2JN-3DLGP  [C402H22]  85 38.73 90 top
C268  SC100P50V2JN-3DLGP  [C402H22]  82.96 38.73 270 top
C271  SCD1U16V2KX-3DLGP  [C402H22]  105.19 28.83 270 top
C311  SC4D7U6D3V3KX-DLGP  [C603H36]  172.37 138.56 180 bottom
C312  SCD1U16V2KX-3DLGP  [C402H22]  173.39 139.45 0 bottom
C316  SCD1U16V2KX-3DLGP  [C402H22]  83.47 196.85 0 bottom
C324  SCD1U16V2KX-3DLGP  [C402H22]  179.87 140.08 180 bottom
C325  SCD1U16V2KX-3DLGP  [C402H22]  178.98 140.08 180 bottom
C329  SCD1U16V2KX-3DLGP  [C402H22]  174.79 139.83 90 bottom
C330  SC4D7U6D3V3KX-DLGP  [C603H36]  174.4 137.85 270 bottom
C419  SCD1U16V2KX-3DLGP  [C402H22]  116.11 39.12 180 bottom
C450  SC10U10V5KX-2DLGP  [C805H50]  166.1 84.45 90 top
C474  SC1U10V2KX-1DLGP  [C402H22]  160.18 74.42 270 bottom
C478  SC10U6D3V3MX-DL-GP  [C603H36]  160.18 75.69 270 bottom
C483  SCD1U16V2KX-3DLGP  [C402H22]  167.29 71.25 90 top
C485  SC10U6D3V3MX-DL-GP  [C603H36]  167.29 70.23 90 top
C486  SCD1U16V2KX-3DLGP  [C402H22]  48.42 116.33 90 bottom
C489  SCD1U16V2KX-3DLGP  [C402H22]  49.41 90.6 0 top
C493  SC10U6D3V3MX-DL-GP  [C603H36]  164.5 70.23 270 top
C495  SCD1U16V2KX-3DLGP  [C402H22]  164.5 71.25 90 top
C500  SCD1U16V2KX-3DLGP  [C402H22]  48.42 117.22 270 top
C501  SCD1U16V2KX-3DLGP  [C402H22]  82.84 216.28 90 top
C509  SC10U6D3V3MX-DL-GP  [C603H36]  157.69 66.19 0 top
C514  SCD1U16V2KX-3DLGP  [C402H22]  48.42 116.33 270 top
C516  SCD1U16V2KX-3DLGP  [C402H22]  158.78 66.55 0 top
C524  SC2200P50V2KX-2DLGP  [C402H22]  140.11 45.34 180 bottom
C529  SCD1U16V2KX-3DLGP  [C402H22]  48.04 108.33 180 bottom
C540  SCD1U16V2KX-3DLGP  [C402H22]  48.67 106.81 270 top
C557  SCD1U16V2KX-3DLGP  [C402H22]  48.42 115.44 90 bottom
C559  SCD1U16V2KX-3DLGP  [C402H22]  64.42 104.52 180 bottom
C570  SCD1U16V2KX-3DLGP  [C402H22]  40.29 13.13 90 bottom
C572  SCD1U16V2KX-3DLGP  [C402H22]  41.44 11.38 90 top
C574  SCD1U16V2KX-3DLGP  [C402H22]  39.4 14.02 90 bottom
C579  SC2D2U10V3KX-1DLGP-U  [C603H36]  43.85 9.53 270 top
C580  SCD1U16V2KX-3DLGP  [C402H22]  38.01 12.57 0 bottom
C582  SCD1U16V2KX-3DLGP  [C402H22]  32.88 25.2 270 top
C583  SCD1U16V2KX-3DLGP  [C402H22]  40.42 15.24 90 bottom
C584  SCD1U16V2KX-3DLGP  [C402H22]  40.29 12.24 90 bottom
C585  SCD1U16V2KX-3DLGP  [C402H22]  30.13 25.15 90 bottom
C587  SCD1U16V2KX-3DLGP  [C402H22]  36.74 17.53 180 bottom
C591  SC1U10V2KX-1DLGP  [C402H22]  44.23 6.05 180 bottom
C592  SC10U10V5KX-2DLGP  [C805H50]  26.96 6.1 180 bottom
C593  SC1U10V2KX-1DLGP  [C402H22]  45.25 5.97 0 top
C595  SCD1U16V2KX-3DLGP  [C402H22]  39.2 7.39 90 bottom
C597  SCD1U50V3KX-DL-GP  [C603H35]  64.3 23.62 270 bottom
C612  SCD1U16V2KX-3DLGP  [C402H22]  48.29 99.82 270 top
C616  SCD1U16V2KX-3DLGP  [C402H22]  48.42 88.77 90 bottom
C623  SCD1U16V2KX-3DLGP  [C402H22]  48.42 87.88 90 bottom
C627  SCD1U16V2KX-3DLGP  [C402H22]  48.42 114.55 90 bottom
C705  SC10U6D3V3MX-DL-GP  [C603H36]  93.25 171.45 90 bottom
C706  SC10U6D3V3MX-DL-GP  [C603H36]  106.84 181.99 90 bottom
C707  SC10U6D3V3MX-DL-GP  [C603H36]  106.84 179.45 90 bottom
C708  SC10U6D3V3MX-DL-GP  [C603H36]  106.84 178.18 90 bottom
C709  SC10U6D3V3MX-DL-GP  [C603H36]  95.41 175.9 0 bottom
C710  SC10U6D3V3MX-DL-GP  [C603H36]  94.27 162.94 90 bottom
C715  SC1U10V2KX-1DLGP  [C402H22]  92.44 168.71 180 bottom
C716  SC1U10V2KX-1DLGP  [C402H22]  52.87 137.92 180 top
C717  SC1U10V2KX-1DLGP  [C402H22]  73.31 157.99 270 bottom
C718  SC1U10V2KX-1DLGP  [C402H22]  90.89 159.13 180 bottom
C719  SC10U6D3V2MX-2-GP  [C402-TO0D2H28]  93.35 168.66 180 bottom
C720  SC1U10V2KX-1DLGP  [C402H22]  78.39 157.23 180 bottom
C742  SC1U10V2KX-1DLGP  [C402H22]  90.2 161.54 90 bottom
C743  SC1U10V2KX-1DLGP  [C402H22]  93.25 173.35 90 bottom
C744  SC1U10V2KX-1DLGP  [C402H22]  93.63 166.75 0 bottom
C745  SC1U10V2KX-1DLGP  [C402H22]  91.35 166.24 90 bottom
C747  SC4D7U6D3V3KX-DLGP  [C603H36]  43.09 143.76 180 top
C749  SC4D7U6D3V3KX-DLGP  [C603H36]  57.82 141.35 0 top
C750  SC10U6D3V2MX-2-GP  [C402-TO0D2H28]  48.8 137.92 0 top
C752  SC47P50V2JN-5DLGP  [C402H22]  97.21 106.66 0 top
C753  SCD1U10V2KX-5DLGP  [C402H22]  85 92.08 0 bottom
C755  SCD01U50V2KX-1DLGP  [C402H22]  92.24 83.06 270 bottom
C756  SC12P50V2JN-DL-GP  [C402H22]  97.34 108.82 0 top
C757  SC12P50V2JN-DL-GP  [C402H22]  97.34 110.85 180 top
C758  SC1U10V2KX-1DLGP  [C402H22]  91.12 101.96 0 bottom
C759  SC1U10V2KX-1DLGP  [C402H22]  90.23 101.96 0 bottom
C760  SC1U10V2KX-1DLGP  [C402H22]  78.93 114.07 90 top
C761  SC1U10V2KX-1DLGP  [C402H22]  74.71 114.3 90 bottom
C762  SC120P50V2JN-1-DL-GP  [C402H22]  82.58 79.5 180 top
C763  SCD1U16V2KX-3DLGP  [C402H22]  87.92 85.98 90 top
C764  SCD1U16V2KX-3DLGP  [C402H22]  77 84.96 90 top
C765  SC1U10V2KX-1DLGP  [C402H22]  90.71 70.99 180 top
C766  SC1U10V2KX-1DLGP  [C402H22]  79.15 105.92 270 bottom
C767  SC1U10V2KX-1DLGP  [C402H22]  74.33 98.55 90 bottom
C768  SC1U10V2KX-1DLGP  [C402H22]  79.15 104.14 270 bottom
C769  SC1U10V2KX-1DLGP  [C402H22]  76.51 92.31 180 bottom
C770  SC1U10V2KX-1DLGP  [C402H22]  75.11 101.83 90 bottom
C771  SC4D7U6D3V3KX-DLGP  [C603H36]  48.17 83.95 90 bottom
C772  SC22U6D3V5MX-2DLGP  [C805H54]  48.04 85.6 90 bottom
C773  SC1U10V2KX-1DLGP  [C402H22]  74.73 100.31 90 bottom
C774  SCD1U16V2KX-3DLGP  [C402H22]  78.9 96.9 270 bottom
C775  SC1U10V2KX-1DLGP  [C402H22]  77.88 93.73 270 bottom
C776  SC1U10V2KX-1DLGP  [C402H22]  62.07 97.02 0 bottom
C777  SC1U10V2KX-1DLGP  [C402H22]  61.52 102.72 90 bottom
C778  SC1U10V2KX-1DLGP  [C402H22]  64.55 101.98 0 bottom
C779  SC1U10V2KX-1DLGP  [C402H22]  87.66 102.52 180 bottom
C780  SC4D7U6D3V3KX-DLGP  [C603H36]  93 102.36 90 bottom
C781  SCD1U16V2KX-3DLGP  [C402H22]  88.55 102.52 180 bottom
C782  SC1U10V2KX-1DLGP  [C402H22]  87.66 99.98 180 bottom
C783  SC1U10V2KX-1DLGP  [C402H22]  88.57 99.98 180 bottom
C784  SC4D7U6D3V3KX-DLGP  [C603H36]  90.35 100.31 270 bottom
C785  SC1U10V2KX-1DLGP  [C402H22]  71.56 85.96 270 top
C786  SC1U10V2KX-1DLGP  [C402H22]  80.17 88.27 90 bottom
C787  SC4D7U6D3V3KX-DLGP  [C603H36]  71.18 83.93 270 top
C788  SC4D7U6D3V3KX-DLGP  [C603H36]  73.97 83.93 90 top
C789  SCD1U16V2KX-3DLGP  [C402H22]  71.56 85.07 270 top
C790  SCD1U16V2KX-3DLGP  [C402H22]  80.17 89.15 90 bottom
C791  SCD1U16V2KX-3DLGP  [C402H22]  80.17 90.04 90 bottom
C792  SCD1U16V2KX-3DLGP  [C402H22]  73.59 85.07 90 top
C793  SC1U10V2KX-1DLGP  [C402H22]  73.59 85.96 90 top
C794  SC1U10V2KX-1DLGP  [C402H22]  98.08 112.39 90 top
C795  SC1U10V2KX-1DLGP  [C402H22]  98.08 113.28 90 top
C796  SC1U10V2KX-1DLGP  [C402H22]  98.08 114.17 90 top
C797  SC4D7U6D3V3KX-DLGP  [C603H36]  98.2 115.32 90 top
C798  SC1U10V2KX-1DLGP  [C402H22]  81.34 103.38 90 bottom
C799  SC1U10V2KX-1DLGP  [C402H22]  80.68 107.57 270 bottom
C800  SC1U10V2KX-1DLGP  [C402H22]  81.31 106.68 270 bottom
C801  SC1U10V2KX-1DLGP  [C402H22]  81.82 105.16 0 bottom
C802  SC1U10V2KX-1DLGP  [C402H22]  82.71 105.16 0 bottom
C803  SC1U10V2KX-1DLGP  [C402H22]  83.6 105.16 0 bottom
C804  SC4D7U6D3V3KX-DLGP  [C603H36]  84.62 105.41 0 bottom
C805  SC1U10V2KX-1DLGP  [C402H22]  86.9 98.55 270 bottom
C806  SC1U10V2KX-1DLGP  [C402H22]  79.15 99.6 180 bottom
C807  SC1U10V2KX-1DLGP  [C402H22]  79.66 98.17 90 bottom
C808  SC1U10V2KX-1DLGP  [C402H22]  84.74 94.74 180 bottom
C809  SC1U10V2KX-1DLGP  [C402H22]  83.6 108.97 180 bottom
C810  SC4D7U6D3V3KX-DLGP  [C603H36]  80.93 110.62 0 bottom
C811  SC4D7U6D3V3KX-DLGP  [C603H36]  82.2 110.62 0 bottom
C812  SC22U6D3V3MX-1-DL-GP  [C603H40]  79.18 102.34 0 bottom
C813  SC1U10V2KX-1DLGP  [C402H22]  86.27 95.25 270 bottom
C814  SC1U10V2KX-1DLGP  [C402H22]  86.77 96.9 270 bottom
C815  SC1U10V2KX-1DLGP  [C402H22]  85.38 100.08 270 bottom
C816  SC1U10V2KX-1DLGP  [C402H22]  82.58 101.73 270 bottom
C817  SC1U10V2KX-1DLGP  [C402H22]  83.6 98.17 90 bottom
C818  SC1U10V2KX-1DLGP  [C402H22]  84.61 96.33 270 bottom
C819  SC1U10V2KX-1DLGP  [C402H22]  84.61 97.29 270 bottom
C820  SCD1U16V2KX-3DLGP  [C402H22]  83.35 100.08 90 bottom
C821  SCD1U16V2KX-3DLGP  [C402H22]  86.16 101.71 270 bottom
C822  SC22U6D3V3MX-1-DL-GP  [C603H40]  82.96 95.12 90 bottom
C823  SC1U10V2KX-1DLGP  [C402H22]  81.63 98.17 270 bottom
C824  SC1U10V2KX-1DLGP  [C402H22]  81.06 96.57 270 bottom
C825  SC1U10V2KX-1DLGP  [C402H22]  89.57 95.89 270 bottom
C826  SCD1U16V2KX-3DLGP  [C402H22]  89.57 96.77 270 bottom
C827  SC1U10V2KX-1DLGP  [C402H22]  93.63 96.01 180 bottom
C828  SC4D7U6D3V3KX-DLGP  [C603H36]  89.95 94.74 270 bottom
C829  SCD1U16V2KX-3DLGP  [C402H22]  92.72 96.01 180 bottom
C830  SC4D7U6D3V3KX-DLGP  [C603H36]  94.65 95.63 180 bottom
C835  SC1U10V2KX-1DLGP  [C402H22]  46.13 114.05 180 top
C836  SCD1U16V2KX-3DLGP  [C402H22]  162.34 91.19 0 top
C839  SC68P50V2JN-1DLGP  [C402H22]  85.63 79.5 0 top
C862  SCD1U50V3KX-DL-GP  [C603H35]  84.62 196.47 180 bottom
C863  SC1U10V2KX-1DLGP  [C402H22]  39.66 5.97 0 top
C864  SC1U10V2KX-1DLGP  [C402H22]  153.32 206.88 270 bottom
C865  SCD22U25V3KX-DL-GP  [C603H36]  127.41 12.45 90 bottom
C1039  SC1U10V2KX-1DLGP  [C402H22]  71.03 166.75 90 bottom
C1040  SC1U10V2KX-1DLGP  [C402H22]  72.55 169.29 270 bottom
C1041  SC1U10V2KX-1DLGP  [C402H22]  74.71 162.31 270 bottom
C1042  SC1U10V2KX-1DLGP  [C402H22]  87.79 164.08 270 bottom
C1043  SC1U10V2KX-1DLGP  [C402H22]  87.79 164.97 270 bottom
C1044  SC22U6D3V3MX-1-DL-GP  [C603H40]  79.03 167.41 0 bottom
C1045  SC22U6D3V3MX-1-DL-GP  [C603H40]  80.2 167.41 0 bottom
C1046  SC22U6D3V3MX-1-DL-GP  [C603H40]  81.36 167.41 0 bottom
C1047  SC22U6D3V3MX-1-DL-GP  [C603H40]  82.53 167.41 0 bottom
C1048  SC22U6D3V3MX-1-DL-GP  [C603H40]  83.7 167.41 0 bottom
C1049  SC1U10V2KX-1DLGP  [C402H22]  72.55 168.4 270 bottom
C1050  SC1U10V2KX-1DLGP  [C402H22]  76.61 168.91 0 bottom
C1051  SC1U10V2KX-1DLGP  [C402H22]  76.11 162.94 180 bottom
C1052  SC1U10V2KX-1DLGP  [C402H22]  72.85 174.62 0 bottom
C1053  SC22U6D3V3MX-1-DL-GP  [C603H40]  84.87 167.41 0 bottom
C1054  SC1U10V2KX-1DLGP  [C402H22]  56.68 175.64 180 top
C1055  SC1U10V2KX-1DLGP  [C402H22]  60.74 175.64 180 top
C1136  SC1U10V2KX-1DLGP  [C402H22]  81.44 179.71 90 bottom
C1137  SC1U10V2KX-1DLGP  [C402H22]  81.44 181.36 90 bottom
C1138  SC1U10V2KX-1DLGP  [C402H22]  79.54 182.75 90 bottom
C1139  SC1U10V2KX-1DLGP  [C402H22]  80.93 195.33 180 top
C1140  SC1U10V2KX-1DLGP  [C402H22]  81.44 183.39 90 bottom
C1141  SC1U10V2KX-1DLGP  [C402H22]  83.35 180.72 270 bottom
C1142  SC1U10V2KX-1DLGP  [C402H22]  83.22 182.5 270 bottom
C1143  SC1U10V2KX-1DLGP  [C402H22]  79.92 195.33 180 top
C1144  SC1U10V2KX-1DLGP  [C402H22]  79.54 181.86 90 bottom
C1145  SC1U10V2KX-1DLGP  [C402H22]  83.09 184.4 90 bottom
C1148  SC22U6D3V3MX-1-DL-GP  [C603H40]  84.28 161.16 0 bottom
C1149  SC22U6D3V3MX-1-DL-GP  [C603H40]  78.44 161.16 0 bottom
C1150  SC22U6D3V3MX-1-DL-GP  [C603H40]  79.61 161.16 0 bottom
C1151  SC1U10V2KX-1DLGP  [C402H22]  87.79 163.22 270 bottom
C1152  SC1U10V2KX-1DLGP  [C402H22]  87.79 161.42 270 bottom
C1153  SC1U10V2KX-1DLGP  [C402H22]  87.41 168.53 0 bottom
C1154  SC1U10V2KX-1DLGP  [C402H22]  87.13 162.36 270 bottom
C1173  SC1U10V2KX-1DLGP  [C402H22]  79.03 155.63 90 bottom
C1174  SC1U10V2KX-1DLGP  [C402H22]  56.34 139.32 90 top
C1175  SC1U10V2KX-1DLGP  [C402H22]  80.96 155.63 90 bottom
C1179  SC10U6D3V2MX-2-GP  [C402-TO0D2H28]  80.6 157.1 90 bottom
C1181  SC1U10V2KX-1DLGP  [C402H22]  77.63 154.91 0 bottom
C1182  SC47U4V3MX-1-GP  [C603H40]  55.66 138.3 90 top
C1184  SC22U6D3V3MX-1-DL-GP  [C603H40]  42.96 171.2 180 top
C1185  SC22U6D3V3MX-1-DL-GP  [C603H40]  54.8 162.97 0 top
C1186  SC22U6D3V3MX-1-DL-GP  [C603H40]  83.12 161.16 0 bottom
C1187  SC1U10V2KX-1DLGP  [C402H22]  76.11 161.04 0 bottom
C1201  SCD1U16V2KX-3DLGP  [C402H22]  138.97 148.46 180 bottom
C1202  SCD1U16V2KX-3DLGP  [C402H22]  139.86 148.46 180 bottom
C1203  SCD1U16V2KX-3DLGP  [C402H22]  127.8 125.6 180 bottom
C1204  SCD1U16V2KX-3DLGP  [C402H22]  131.35 193.04 0 bottom
C1205  SC2D2U10V3KX-1DLGP-U  [C603H36]  133.51 193.29 0 bottom
C1206  SCD1U16V2KX-3DLGP  [C402H22]  130.46 193.04 0 bottom
C1207  SC10U6D3V3MX-DL-GP  [C603H36]  131.1 162.43 270 bottom
C1208  SC10U6D3V3MX-DL-GP  [C603H36]  139.61 165.61 90 bottom
C1209  SC10U6D3V3MX-DL-GP  [C603H36]  139.61 161.93 90 bottom
C1212  SC1U10V2KX-1DLGP  [C402H22]  139.61 163.7 90 bottom
C1213  SC1U10V2KX-1DLGP  [C402H22]  139.61 156.84 90 bottom
C1214  SC1U10V2KX-1DLGP  [C402H22]  139.73 125.6 180 bottom
C1215  SC1U10V2KX-1DLGP  [C402H22]  138.84 125.6 180 bottom
C1216  SC1U10V2KX-1DLGP  [C402H22]  137.96 125.6 180 bottom
C1217  SCD1U16V2KX-3DLGP  [C402H22]  139.48 181.23 90 bottom
C1218  SCD1U16V2KX-3DLGP  [C402H22]  141.89 148.46 180 bottom
C1219  SC1U10V2KX-1DLGP  [C402H22]  130.97 153.54 270 bottom
C1220  SC1U10V2KX-1DLGP  [C402H22]  131.61 125.6 180 bottom
C1221  SC1U10V2KX-1DLGP  [C402H22]  130.72 125.6 180 bottom
C1222  SC1U10V2KX-1DLGP  [C402H22]  129.83 125.6 180 bottom
C1223  SC1U10V2KX-1DLGP  [C402H22]  130.97 163.83 270 bottom
C1224  SC1U10V2KX-1DLGP  [C402H22]  130.97 160.53 270 bottom
C1225  SC1U10V2KX-1DLGP  [C402H22]  139.61 160.27 90 bottom
C1226  SC1U10V2KX-1DLGP  [C402H22]  139.61 155.07 90 bottom
C1227  SC1U10V2KX-1DLGP  [C402H22]  130.97 157.23 270 bottom
C1228  SC10U6D3V3MX-DL-GP  [C603H36]  130.97 167.13 270 bottom
C1229  SC10U6D3V3MX-DL-GP  [C603H36]  139.61 158.62 90 bottom
C1230  SC10U6D3V3MX-DL-GP  [C603H36]  131.1 158.88 270 bottom
C1231  SC10U6D3V3MX-DL-GP  [C603H36]  131.1 155.45 270 bottom
C1232  SC10U6D3V3MX-DL-GP  [C603H36]  130.97 151.64 270 bottom
C1233  SC1U10V2KX-1DLGP  [C402H22]  146.46 154.69 270 bottom
C1234  SC1U10V2KX-1DLGP  [C402H22]  146.46 157.86 270 bottom
C1235  SC1U10V2KX-1DLGP  [C402H22]  154.85 151.38 90 bottom
C1236  SC1U10V2KX-1DLGP  [C402H22]  154.85 153.16 90 bottom
C1237  SC1U10V2KX-1DLGP  [C402H22]  132.49 125.6 180 bottom
C1238  SC1U10V2KX-1DLGP  [C402H22]  137.07 125.6 180 bottom
C1239  SC1U10V2KX-1DLGP  [C402H22]  154.85 156.84 90 bottom
C1240  SC1U10V2KX-1DLGP  [C402H22]  154.85 160.4 90 bottom
C1241  SC10U6D3V3MX-DL-GP  [C603H36]  154.85 158.62 90 bottom
C1245  SC10U6D3V3MX-DL-GP  [C603H36]  154.85 154.94 90 bottom
C1246  SC10U6D3V3MX-DL-GP  [C603H36]  146.34 152.91 270 bottom
C1247  SC22U6D3V5MX-2DLGP  [C805H54]  90.84 204.22 90 bottom
C1256  SCD022U16V2KX-3DLGP  [C402H22]  129.45 194.94 0 bottom
C1257  SCD022U16V2KX-3DLGP  [C402H22]  145.07 150.24 0 bottom
C1301  SCD1U16V2KX-3DLGP  [C402H22]  153.96 181.61 180 bottom
C1302  SCD1U16V2KX-3DLGP  [C402H22]  145.96 193.17 0 bottom
C1303  SC22U6D3V5MX-2DLGP  [C805H54]  90.84 202.18 90 bottom
C1305  SC2D2U10V3KX-1DLGP-U  [C603H36]  147.86 193.29 0 bottom
C1306  SCD1U16V2KX-3DLGP  [C402H22]  155.48 146.43 270 bottom
C1308  SCD1U16V2KX-3DLGP  [C402H22]  155.48 147.32 270 bottom
C1309  SCD1U16V2KX-3DLGP  [C402H22]  155.48 148.21 270 bottom
C1310  SCD1U16V2KX-3DLGP  [C402H22]  146.85 193.17 0 bottom
C1311  SCD1U16V2KX-3DLGP  [C402H22]  147.1 127.76 180 bottom
C1312  SC10U6D3V3MX-DL-GP  [C603H36]  146.34 156.46 270 bottom
C1313  SC10U6D3V3MX-DL-GP  [C603H36]  146.34 165.1 270 bottom
C1314  SC1U10V2KX-1DLGP  [C402H22]  146.46 163.19 270 bottom
C1315  SC1U10V2KX-1DLGP  [C402H22]  154.85 163.96 90 bottom
C1316  SC10U6D3V3MX-DL-GP  [C603H36]  154.85 162.05 90 bottom
C1317  SC10U6D3V3MX-DL-GP  [C603H36]  146.34 160.66 270 bottom
C1318  SC10U6D3V3MX-DL-GP  [C603H36]  154.85 165.74 90 bottom
C1319  SC1U10V2KX-1DLGP  [C402H22]  147.1 125.6 180 bottom
C1320  SC1U10V2KX-1DLGP  [C402H22]  151.93 125.48 180 bottom
C1321  SC1U10V2KX-1DLGP  [C402H22]  152.81 125.48 180 bottom
C1322  SC1U10V2KX-1DLGP  [C402H22]  153.83 125.48 180 bottom
C1323  SC1U10V2KX-1DLGP  [C402H22]  154.72 125.48 180 bottom
C1324  SC1U10V2KX-1DLGP  [C402H22]  144.43 125.6 180 bottom
C1325  SC1U10V2KX-1DLGP  [C402H22]  145.32 125.6 180 bottom
C1326  SC1U10V2KX-1DLGP  [C402H22]  146.21 125.6 180 bottom
C1328  SCD022U16V2KX-3DLGP  [C402H22]  143.8 195.07 0 bottom
C1491  SC1U10V2KX-1DLGP  [C402H22]  162.21 70.61 0 top
C1615  SC2D2U10V3KX-1DLGP-U  [C603H36]  146.46 205.99 90 bottom
C1616  SC1U10V2KX-1DLGP  [C402H22]  144.69 204.72 0 bottom
C1617  SCD1U16V2KX-3DLGP  [C402H22]  146.46 204.98 90 bottom
C1698  SC1U10V2KX-1DLGP  [C402H22]  145.83 5.46 180 bottom
C1699  SC1U10V2KX-1DLGP  [C402H22]  146.72 11.3 270 bottom
C1700  SC1U6D3V2KX-DLGP  [C402H22]  144.13 8 180 bottom
C1701  SCD1U16V2KX-3DLGP  [C402H22]  151.42 9.91 270 bottom
C1742  SCD1U16V2KX-3DLGP  [C402H22]  121.95 204.22 0 top
C1743  SC10U6D3V3MX-DL-GP  [C603H36]  123.1 204.22 0 top
